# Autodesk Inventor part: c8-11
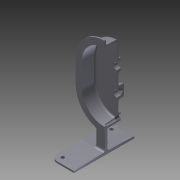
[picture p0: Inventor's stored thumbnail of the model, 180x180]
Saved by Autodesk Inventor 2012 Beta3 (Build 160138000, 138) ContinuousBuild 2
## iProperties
Created: 2010-12
Part Number: c8-11
Document SubType Name: Modeling
Designer: Thom Tremblay
Density: 7.25 g/cm^3
Material: Cast Iron
Mass: 1233.53 g
Surface Area: 883.619 cm^2
Volume: 170.142 cm^3
Author: Thom Tremblay
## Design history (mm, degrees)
sketch "Sketch1"
  geometry: L1 (-50, -50)-(-50, 0); L2 (50, 0)-(50, -50); L3 (-60, 0)-(-60, -50); L4 (60, -50)-(60, 0); A1 r 50 centre (0, 0) between (50, 0) and (-50, 0); A2 r 50 centre (0, -50) between (-50, -50) and (50, -50); A3 r 60 centre (0, -50) between (-60, -50) and (60, -50); A4 r 60 centre (0, 0) between (60, 0) and (-60, 0); 1 further point
  constraints: 8 end point, 8 point on circle, 4 centre point, 4 tangent, 2 parallel, 1 coincident, 1 vertical, 3 other
  dimensions: "d0" = 50 distance of L2.start L2.end; "d1" = 50 radius of A1; "d2" = 10 radial gap between concentric circles of A4 A1
extrude "Extrusion1" new body sketch "Sketch1" distance "d3" = 30; taper "d4" = -2 deg
fillet "Fillet1" dims "d7" = 6
shell "Shell3" dims "d132" = 3
extrude "Extrusion2" join sketch "Sketch1" distance "d5" = 4; taper "d6" = -2 deg
fillet "Fillet12" dims "d133" = 2
fillet "Fillet13" dims "d134" = 1
workplane "Work Plane2"
sketch "Sketch7"
  geometry: C1 r 7.5 at (0, -95); 1 further point
  constraints: 1 centre point, 1 vertical alignment
  dimensions: "d64" = 15 diameter of C1; "d65" = 95 distance of point (0, 0) C1.centre
extrude "Extrusion8" join sketch "Sketch7" stored distance "d66" = 12.7; taper "d67" = 2 deg
fillet "Fillet2" dims "d9" = 3, "d10" = 1
hole "Hole3" diameter "d70" = 8; stored, may be unused: countersink angle "d74" = 82 deg, drill point angle "d76" = 118 deg; dims "d68" = 10, "d69" = 10, "d71" = 9, "d72" = 9.525, "d73" = 6.35, "d75" = 30, "d77" = 0.62479, "d78" = 7.985
workplane "Work Plane1"
sketch "Sketch2"
  geometry: L1 (-20.917, -1.5)-(20.917, -1.5); L2 (20.917, -1.5)-(20.219, -21.5); L3 (20.219, -21.5)-(16.219, -21.5); L4 (16.219, -21.5)-(15.695, -6.5); L5 (15.695, -6.5)-(-15.695, -6.5); L6 (-15.695, -6.5)-(-16.219, -21.5); L7 (-16.219, -21.5)-(-20.219, -21.5); L8 (-20.219, -21.5)-(-20.917, -1.5); L9 (-16.219, -21.5)-(16.219, -21.5); 3 further points
  constraints: 18 end point, 3 parallel, 2 equal length, 2 midpoint, 2 vertical alignment, 1 collinear, 1 horizontal
  dimensions: "d12" = 4 deg angle of L8 L6; "d13" = 88 deg angle of L8 L1; "d14" = 1.5 distance from line of point (0, 0) L1; "d15" = 20 vertical distance of L1.end L2.end; "d16" = 4 distance of L2.end L3.end; "d17" = 5 distance between parallel lines of L1 L5
extrude "Extrusion3" join sketch "Sketch2" stored distance "d18" = 27.94; taper "d19" = 0 deg
sketch "Sketch3"
  geometry: L1 (-70, -150)-(70, -150) reference; L2 (-50, -150)-(50, -150); L3 (50, -150)-(50, -144); L4 (50, -144)-(-50, -144); L5 (-50, -144)-(-50, -150); 2 further points
  constraints: 8 end point, 2 parallel, 1 horizontal, 1 midpoint, 1 perpendicular, 1 point on line, 1 vertical alignment
  dimensions: "d20" = 100 distance of L3.end L4.end; "d21" = 6 distance of L2.end L3.end
extrude "Extrusion4" join sketch "Sketch3" distance "d22" = 63.5; taper "d23" = 0 deg
feature "FaceDraft1" dims angle "d24" = 2 deg
sketch "Sketch4"
  geometry: L1 (-50, -150)-(50, -150) reference; L2 (50, -150)-(50, -143.773) reference; L3 (50, -143.773)-(-50, -143.773) reference; L4 (-50, -143.773)-(-50, -150) reference; 1 further point
extrude "Extrusion5" join sketch "Sketch4" distance "d25" = 63.5; taper "d26" = 0 deg
feature "FaceDraft2" dims angle "d27" = 2 deg
fillet "Fillet3" dims "d28" = 12
fillet "Fillet4"
fillet "Fillet5"
fillet "Fillet6" dims "d29" = 4
fillet "Fillet7" dims "d30" = 4
fillet "Fillet8" dims "d31" = 2
sketch "Sketch5"
  geometry: C1 r 12.5 at (0, 0); 1 further point
  constraints: 1 centre point, 1 coincident
  dimensions: "d32" = 25 diameter of C1
extrude "Extrusion6" join sketch "Sketch5" distance "d33" = 5; taper "d35" = -2 deg; dims "d34" = 8, "d36" = -2 deg
hole "Hole1" diameter "d40" = 14; stored, may be unused: countersink angle "d44" = 82 deg, drill point angle "d46" = 118 deg; dims "d38" = 10, "d39" = 10, "d41" = 19.05, "d42" = 9.525, "d43" = 6.35, "d45" = 25.4
sketch "Sketch10"
  geometry: C1 r 12.5 at (0, -50); A1 r 60 centre (0, -50) between (-60, -50) and (-18.704, -107.01) reference; 1 further point
  constraints: 1 centre point, 1 coincident
  dimensions: "d135" = 25 diameter of C1
extrude "Extrusion9" join sketch "Sketch10" distance "d136" = 12; taper "d137" = -2 deg
fillet "Fillet9" dims "d37" = 3
hole "Hole2" diameter "d55" = 14; stored, may be unused: countersink angle "d59" = 82 deg, drill point angle "d61" = 118 deg; dims "d53" = 10, "d54" = 10, "d56" = 19.05, "d57" = 9.525, "d58" = 6.35, "d60" = 8
hole "Hole4" diameter "d81" = 7; stored, may be unused: countersink angle "d85" = 82 deg, drill point angle "d87" = 118 deg; dims "d79" = 10, "d80" = 10, "d82" = 12.7, "d83" = 12.8778, "d84" = 6.35, "d86" = 30.48
hole "Hole5" diameter "d90" = 7; stored, may be unused: countersink angle "d94" = 82 deg, drill point angle "d96" = 118 deg; dims "d88" = 10, "d89" = 10, "d91" = 12.7, "d92" = 12.8778, "d93" = 6.35, "d95" = 30.48
hole "Hole6" diameter "d99" = 7; stored, may be unused: countersink angle "d103" = 82 deg, drill point angle "d105" = 118 deg; dims "d97" = 10, "d98" = 10, "d100" = 12.7, "d101" = 12.8778, "d102" = 6.35, "d104" = 30.48
hole "Hole7" diameter "d108" = 7; stored, may be unused: countersink angle "d112" = 82 deg, drill point angle "d114" = 118 deg; dims "d106" = 10, "d107" = 10, "d109" = 12.7, "d110" = 12.8778, "d111" = 6.35, "d113" = 30.48
fillet "Fillet11" dims "d122" = 1
node "Hole10"
chamfer "Chamfer1" distance "d138" = 0.6; stored, may be unused: second distance "d139" = 2, angle "d140" = 45 deg
split "Split1"
body "Solid1"
node "Projected Loop1"
sketch "Sketch9"
  geometry: 8 further points
hole "Hole9" sketch "Sketch9" diameter "d123" = 3.242; stored, may be unused: countersink angle "d127" = 82 deg, drill point angle "d129" = 0 deg; dims "d124" = 19.05, "d125" = 9.525, "d126" = 6.35, "d128" = 25.4
other parameters: "d63" = -35
